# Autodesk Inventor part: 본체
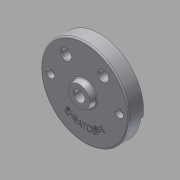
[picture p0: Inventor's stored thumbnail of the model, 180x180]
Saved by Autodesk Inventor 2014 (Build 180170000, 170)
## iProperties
Created: 2015-06
Part Number: 본체
Material: 알루미늄 6061
Document SubType Name: Modeling
Designer: MYHOME
Density: 2.71 g/cm^3
Appearance: 알루미늄 - 평지
Mass: 1084.06 g
Surface Area: 1052.47 cm^2
Volume: 400.022 cm^3
Author: MYHOME
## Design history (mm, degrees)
sketch "스케치2"
  geometry: C1 r 95 at (0, 0); 1 further point
  constraints: 1 centre point, 1 coincident
  dimensions: "d0" = 190 diameter of C1
extrude "돌출1" new body sketch "스케치2" distance "d1" = 32; taper "d2" = 0 deg
sketch "스케치3"
  geometry: C1 r 95 at (0, 0) reference; C2 r 90 at (0, 0)
  constraints: 1 centre point, 1 coincident
  dimensions: "d3" = 180 diameter of C2
extrude "돌출2" cut sketch "스케치3" distance "d4" = 25; taper "d5" = 0 deg
sketch "스케치4"
  geometry: L1 (0, 0)-(95, 0); L2 (0, 0)-(-98, 0); L3 (0, 0)-(-94.075, -13.221); L4 (0, 0)-(94.075, -13.221); A1 r 90 centre (0, 0) between (-89.124, -12.526) and (89.124, -12.526) reference; A2 r 95 centre (0, 0) between (95, 0) and (-94.075, -13.221) reference; 2 further points
  constraints: 8 end point, 5 point on circle, 2 coincident, 2 point on line, 1 collinear, 1 horizontal
  dimensions: "d7" = 8 deg angle of L2 L3; "d8" = 8 deg angle of L1 L4
extrude "돌출3" cut sketch "스케치4" distance "d9" = 5; taper "d10" = 0 deg
sketch "스케치5"
  geometry: L1 (-88.566, 16)-(-38.833, 16); L2 (38.833, 16)-(88.566, 16); A1 r 90 centre (0, 0) between (-88.566, 16) and (88.566, 16) reference; A2 r 42 centre (0, 0) between (38.833, 16) and (-38.833, 16)
  constraints: 4 end point, 4 point on circle, 2 horizontal, 1 centre point, 1 coincident
  dimensions: "d11" = 84 diameter of A2; "d13" = 16 distance from line of L1 A1.centre; "d14" = 16 distance from line of A1.centre L2
extrude "돌출4" join sketch "스케치5" distance "d15" = 7; taper "d16" = 0 deg
sketch "스케치6"
  geometry: L1 (-38.833, 16)-(-88.566, 16) reference; L2 (-59, -19)-(-59, -14); L3 (-41, -19)-(-41, -14); L4 (41, -19)-(41, -14); L5 (59, -19)-(59, -14); A1 r 90 centre (0, 0) between (-88.566, 16) and (88.566, 16) reference; A2 r 59 centre (0, -19) between (-59, -19) and (59, -19); A3 r 41 centre (0, -19) between (-41, -19) and (41, -19); A4 r 9 centre (-50, -14) between (-41, -14) and (-59, -14); A5 r 9 centre (50, -14) between (59, -14) and (41, -14)
  constraints: 8 end point, 8 point on circle, 4 centre point, 4 horizontal alignment, 4 tangent, 3 parallel, 1 perpendicular, 1 vertical alignment
  dimensions: "d17" = 59 radius of A2; "d18" = 19 distance of A1.centre A2.centre; "d19" = 41 radius of A3; "d20" = 18 diameter of A4; "d21" = 18 diameter of A5; "d22" = 5 distance of L3.start L3.end; "d23" = 5 distance of L2.start L2.end; "d24" = 5 distance of L5.start L5.end; "d25" = 5 distance of L4.start L4.end
extrude "돌출5" cut sketch "스케치6" distance "d26" = 7; taper "d27" = 0 deg
sketch "스케치7"
  geometry: C1 r 95 at (0, 0) reference; C2 r 26 at (0, 0)
  constraints: 1 centre point, 1 coincident
  dimensions: "d28" = 52 diameter of C2
extrude "돌출6" join sketch "스케치7" distance "d29" = 12; taper "d30" = -15 deg
sketch "스케치10"
  geometry: L1 (38.833, 16)-(88.566, 16) reference; L2 (-40, 52)-(40, 52); C1 r 15 at (-40, 52); C2 r 15 at (40, 52); A1 r 42 centre (0, 0) between (38.833, 16) and (-38.833, 16) reference; 1 further point
  constraints: 2 centre point, 2 end point, 1 horizontal alignment, 1 midpoint, 1 parallel, 1 vertical alignment
  dimensions: "d37" = 80 distance of L2.end L2.start; "d38" = 30 diameter of C1; "d39" = 30 diameter of C2; "d40" = 52 distance of point (0, 52) A1.centre
extrude "돌출9" join sketch "스케치10" distance "d41" = 28; taper "d42" = 0 deg
sketch "스케치12"
  geometry: C1 r 35 at (0, 0); A1 r 42 centre (0, 0) between (38.833, 16) and (-38.833, 16) reference
  constraints: 1 centre point, 1 coincident
  dimensions: "d46" = 70 diameter of C1
extrude "돌출11" join sketch "스케치12" distance "d47" = 10; taper "d48" = -10 deg
sketch "스케치13"
  geometry: C1 r 33.237 at (0, 0) reference; C2 r 25 at (0, 0)
  constraints: 1 centre point, 1 coincident
  dimensions: "d49" = 50 diameter of C2
extrude "돌출12" cut sketch "스케치13" distance "d50" = 15; taper "d51" = 0 deg
sketch "스케치14"
  geometry: C1 r 25 at (0, 0) reference; C2 r 11.5 at (0, 0)
  constraints: 1 centre point, 1 coincident
  dimensions: "d52" = 23 diameter of C2
extrude "돌출13" cut sketch "스케치14" stored distance "d53" = 15; taper "d54" = 0 deg
sketch "스케치15"
  geometry: C1 r 15 at (0, 0) reference; C2 r 15 at (80, 0) reference; C3 r 10 at (0, 0); C4 r 10 at (80, 0); 1 further point
  constraints: 2 centre point, 2 coincident
  dimensions: "d55" = 20 diameter of C3; "d56" = 20 diameter of C4
extrude "돌출14" cut sketch "스케치15" stored distance "d57" = 3; taper "d58" = 0 deg
sketch "스케치16"
  geometry: L1 (-6, -18)-(6, -18); L2 (6, -18)-(6, 18); L3 (6, 18)-(-6, 18); L4 (-6, 18)-(-6, -18); L5 (-6, -18)-(6, 18); L6 (6, -18)-(-6, 18); L7 (100, -6)-(60, -6); L8 (60, -6)-(60, 6); L9 (60, 6)-(100, 6); L10 (100, 6)-(100, -6); L11 (100, -6)-(60, 6); L12 (60, -6)-(100, 6); C1 r 15 at (0, 0) reference; C2 r 10 at (80, 0) reference; C3 r 15 at (80, 0) reference; 1 further point
  constraints: 24 end point, 4 midpoint, 4 parallel, 2 horizontal, 2 perpendicular
  dimensions: "d59" = 12 distance of L2.end L3.end; "d60" = 40 distance of L8.end L9.end; "d61" = 36 distance of L1.end L2.end; "d62" = 12 distance of L7.end L8.end
extrude "돌출15" cut sketch "스케치16" distance "d63" = 3; taper "d64" = 0 deg
sketch "스케치17"
  geometry: L1 (-38.833, 16)-(-88.566, 16) reference; L2 (-74, 0)-(74, 0); C1 r 35 at (0, 0) reference; C2 r 9 at (-74, 0); C3 r 9 at (74, 0); 1 further point
  constraints: 2 centre point, 2 end point, 1 coincident, 1 horizontal alignment, 1 midpoint, 1 parallel
  dimensions: "d65" = 18 diameter of C2; "d66" = 18 diameter of C3; "d67" = 148 distance of L2.end L2.start
extrude "돌출16" join sketch "스케치17" distance "d68" = 18; taper "d69" = 0 deg
sketch "스케치18"
  geometry: C1 r 9 at (0, 0) reference; C2 r 9 at (148, 0) reference; C3 r 5.5 at (0, 0); C4 r 5.5 at (148, 0); 1 further point
  constraints: 2 centre point, 2 coincident
  dimensions: "d70" = 11 diameter of C3; "d71" = 11 diameter of C4
extrude "돌출17" cut sketch "스케치18" distance "d72" = 33; taper "d73" = 0 deg
sketch "스케치20"
  geometry: C1 r 95 at (0, 0) reference; C2 r 68 at (0, 0)
  constraints: 1 centre point, 1 coincident, 1 other
  dimensions: "d76" = 136 diameter of C2
feature "엠보싱1" sketch "스케치20" dims "d77" = 0.5, "d78" = 0
sketch "스케치21"
  geometry: C1 r 5.5 at (-74, 0) reference; C2 r 5.5 at (74, 0) reference; C3 r 9 at (-74, 0); C4 r 9 at (74, 0)
  constraints: 2 centre point, 2 coincident
  dimensions: "d79" = 18 diameter of C3; "d80" = 18 diameter of C4
extrude "돌출18" cut sketch "스케치21" distance "d81" = 11; taper "d82" = 0 deg
fillet "모깎기1" dims "d83" = 10
fillet "모깎기2" dims "d84" = 0.3
fillet "모깎기3" dims "d85" = 3
fillet "모깎기4" dims "d86" = 3
fillet "모깎기5" dims "d87" = 3
fillet "모깎기6" dims "d88" = 3
fillet "모깎기7" dims "d89" = 1
fillet "모깎기8" dims "d90" = 2
chamfer "모따기1" distance "d91" = 1; stored, may be unused: second distance "d92" = 2, angle "d93" = 45 deg
chamfer "모따기2" distance "d94" = 1; stored, may be unused: second distance "d95" = 2, angle "d96" = 45 deg
chamfer "모따기3" distance "d97" = 1; stored, may be unused: second distance "d98" = 2, angle "d99" = 45 deg
node "솔리드1"
node "투영된 루프1"
node "투영된 루프2"
node "투영된 루프3"
other parameters: "d12" = 16
